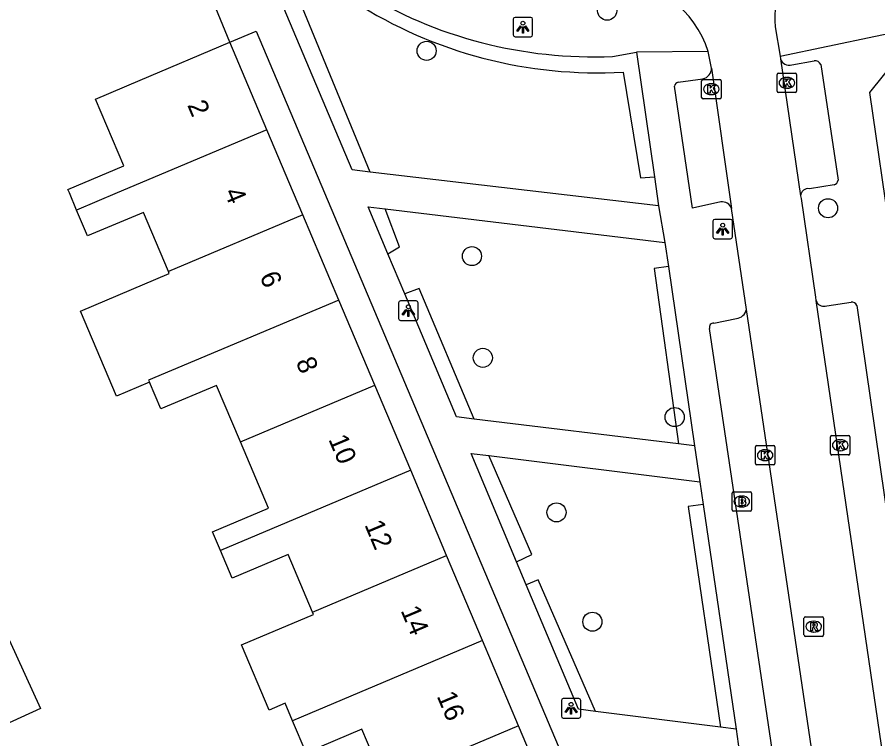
# Model space of a CAD drawing. Extents: x 162172 to 163187, y 382874 to 383684.
# Drawn here: x 162745.12 to 162789.24, y 383222 to 383259.01 of the extents above; entities that cross this region are included whole.
import ezdxf

# ---------------------------------------------------------------- set-up
doc = ezdxf.new("R2010")
doc.units = 0
for name, color, linetype in [('IMGEO_Boom', 7, 'Continuous'), ('IMGEO_Brandkraan', 7, 'Continuous'), ('IMGEO_Haag', 7, 'Continuous'), ('IMGEO_Kolk', 7, 'Continuous'), ('IMGEO_Lichtpunt', 7, 'Continuous'), ('IMGEO_Pand', 7, 'Continuous'), ('IMGEO_Pand_nummerreeks', 7, 'Continuous'), ('IMGEO_Rijbaan_lokaal_open', 7, 'Continuous'), ('IMGEO_Rioolput', 7, 'Continuous'), ('IMGEO_Voetpad_open', 7, 'Continuous')]:
    doc.layers.add(name, color=color, linetype=linetype)

msp = doc.modelspace()

# ---------------------------------------------------------------- linework, layer by layer
at = {"layer": 'IMGEO_Boom'}
for centre in [(162775.367, 383259.341), (162766.112, 383257.287), (162786.691, 383249.213), (162768.437, 383246.757), (162768.995, 383241.541), (162778.829, 383238.501), (162772.772, 383233.614), (162774.61, 383228.007)]:
    msp.add_circle(centre, 0.489, dxfattribs=at)
at = {"layer": 'IMGEO_Brandkraan'}
for p, q in [((162781.77, 383233.746), (162781.77, 383234.598)), ((162781.845, 383234.672), (162782.697, 383234.672)), ((162782.258, 383234.452), (162782.283, 383234.452)), ((162782.771, 383234.598), (162782.771, 383233.746)), ((162782.697, 383233.672), (162781.845, 383233.672)), ((162782.281, 383233.892), (162782.256, 383233.892))]:
    msp.add_line(p, q, dxfattribs=at)
for points in [[(162781.77, 383233.746), (162781.77, 383234.598)], [(162781.845, 383234.672), (162782.697, 383234.672)], [(162782.771, 383234.598), (162782.771, 383233.746)], [(162782.118, 383234.372), (162782.118, 383233.972), (162782.331, 383233.972)], [(162782.349, 383234.372), (162782.118, 383234.372)], [(162782.297, 383234.291), (162782.243, 383234.291), (162782.243, 383234.215)], [(162782.243, 383234.215), (162782.296, 383234.215)], [(162782.305, 383234.139), (162782.243, 383234.139), (162782.243, 383234.058)], [(162782.243, 383234.058), (162782.305, 383234.058)], [(162782.697, 383233.672), (162781.845, 383233.672)]]:
    msp.add_lwpolyline(points, dxfattribs=at)
for centre, radius, start, end in [((162781.847, 383234.596), 0.0765, 91.552, 178.448), ((162781.847, 383234.596), 0.0765, 91.552, 178.448), ((162782.695, 383234.596), 0.0765, 1.552, 88.448), ((162782.695, 383234.596), 0.0765, 1.552, 88.448), ((162782.298, 383234.253), 0.0379, 267.8285, 90.9355), ((162782.306, 383234.098), 0.0404, 269.8759, 90.5077), ((162782.337, 383234.223), 0.251, 268.6676, 293.5347), ((162782.353, 383234.227), 0.145, 59.4692, 91.5367), ((162782.378, 383234.274), 0.0922, 285.5137, 58.1501), ((162782.383, 383234.082), 0.105, 301.3115, 78.989), ((162781.847, 383233.748), 0.0765, 181.552, 268.448), ((162781.847, 383233.748), 0.0765, 181.552, 268.448), ((162782.695, 383233.748), 0.0765, 271.552, 358.448), ((162782.695, 383233.748), 0.0765, 271.552, 358.448)]:
    msp.add_arc(centre, radius, start, end, dxfattribs=at)
for centre, major_axis, ratio, start_param, end_param in [((162782.257, 383234.172), (-0.387, 0.002), 0.722429, 4.712389, 7.853982), ((162782.282, 383234.172), (-0.39, 0.002), 0.717154, 1.570796, 4.712389)]:
    msp.add_ellipse(centre, major_axis=major_axis, ratio=ratio, start_param=start_param, end_param=end_param, dxfattribs=at)
at = {"layer": 'IMGEO_Haag'}
for points in [[(162763.217, 383251.068), (162759.506, 383260.09), (162760.869, 383261.604)], [(162776.18, 383256.197), (162777.082, 383250.77), (162777.789, 383250.819)], [(162764.126, 383246.877), (162764.728, 383247.234), (162763.981, 383249.177)], [(162778.511, 383246.225), (162777.772, 383246.13), (162779.025, 383237.133)], [(162768.556, 383238.403), (162765.727, 383245.101), (162764.994, 383244.816)], [(162770.724, 383231.084), (162771.502, 383231.448), (162769.295, 383236.525)], [(162780.295, 383234.023), (162779.518, 383233.923), (162781.183, 383222.6)], [(162774.776, 383223.407), (162771.823, 383230.155), (162771.221, 383229.897)]]:
    msp.add_lwpolyline(points, dxfattribs=at)
msp.add_arc((162774.845, 383279.215), 23.057, 237.321, 273.3192, dxfattribs=at)
at = {"layer": 'IMGEO_Kolk'}
for p, q in [((162784.081, 383255.217), (162784.081, 383256.069)), ((162784.156, 383256.143), (162785.008, 383256.143)), ((162785.082, 383256.069), (162785.082, 383255.217)), ((162780.209, 383254.892), (162780.209, 383255.744)), ((162780.284, 383255.818), (162781.136, 383255.818)), ((162780.697, 383255.598), (162780.722, 383255.598)), ((162781.21, 383255.744), (162781.21, 383254.892)), ((162784.569, 383255.923), (162784.594, 383255.923)), ((162784.592, 383255.363), (162784.567, 383255.363)), ((162781.136, 383254.818), (162780.284, 383254.818)), ((162780.72, 383255.038), (162780.695, 383255.038)), ((162785.008, 383255.143), (162784.156, 383255.143)), ((162786.89, 383237.558), (162787.742, 383237.558)), ((162786.815, 383236.632), (162786.815, 383237.484)), ((162787.303, 383237.338), (162787.328, 383237.338)), ((162787.816, 383237.484), (162787.816, 383236.632)), ((162782.967, 383236.121), (162782.967, 383236.973)), ((162783.042, 383237.047), (162783.894, 383237.047)), ((162783.455, 383236.827), (162783.48, 383236.827)), ((162783.968, 383236.973), (162783.968, 383236.121)), ((162787.326, 383236.778), (162787.301, 383236.778)), ((162783.478, 383236.267), (162783.453, 383236.267)), ((162787.742, 383236.558), (162786.89, 383236.558)), ((162783.894, 383236.047), (162783.042, 383236.047))]:
    msp.add_line(p, q, dxfattribs=at)
for points in [[(162784.081, 383255.217), (162784.081, 383256.069)], [(162784.156, 383256.143), (162785.008, 383256.143)], [(162785.082, 383256.069), (162785.082, 383255.217)], [(162780.209, 383254.892), (162780.209, 383255.744)], [(162780.284, 383255.818), (162781.136, 383255.818)], [(162781.21, 383255.744), (162781.21, 383254.892)], [(162784.402, 383255.843), (162784.525, 383255.843), (162784.525, 383255.692), (162784.655, 383255.843), (162784.819, 383255.843), (162784.673, 383255.692), (162784.826, 383255.443), (162784.674, 383255.443), (162784.589, 383255.607), (162784.525, 383255.54), (162784.525, 383255.443), (162784.402, 383255.443), (162784.402, 383255.843)], [(162780.53, 383255.518), (162780.653, 383255.518), (162780.653, 383255.367), (162780.783, 383255.518), (162780.947, 383255.518), (162780.801, 383255.367), (162780.954, 383255.118), (162780.802, 383255.118), (162780.717, 383255.282), (162780.653, 383255.215), (162780.653, 383255.118), (162780.53, 383255.118), (162780.53, 383255.518)], [(162781.136, 383254.818), (162780.284, 383254.818)], [(162785.008, 383255.143), (162784.156, 383255.143)], [(162786.89, 383237.558), (162787.742, 383237.558)], [(162786.815, 383236.632), (162786.815, 383237.484)], [(162787.136, 383237.258), (162787.259, 383237.258), (162787.259, 383237.107), (162787.389, 383237.258), (162787.553, 383237.258), (162787.407, 383237.107), (162787.56, 383236.858), (162787.408, 383236.858), (162787.323, 383237.022), (162787.259, 383236.955), (162787.259, 383236.858), (162787.136, 383236.858), (162787.136, 383237.258)], [(162787.816, 383237.484), (162787.816, 383236.632)], [(162782.967, 383236.121), (162782.967, 383236.973)], [(162783.042, 383237.047), (162783.894, 383237.047)], [(162783.288, 383236.747), (162783.411, 383236.747), (162783.411, 383236.596), (162783.541, 383236.747), (162783.705, 383236.747), (162783.559, 383236.596), (162783.712, 383236.347), (162783.56, 383236.347), (162783.475, 383236.511), (162783.411, 383236.444), (162783.411, 383236.347), (162783.288, 383236.347), (162783.288, 383236.747)], [(162783.968, 383236.973), (162783.968, 383236.121)], [(162787.742, 383236.558), (162786.89, 383236.558)], [(162783.894, 383236.047), (162783.042, 383236.047)]]:
    msp.add_lwpolyline(points, dxfattribs=at)
for centre, start, end in [((162784.158, 383256.067), 91.552, 178.448), ((162784.158, 383256.067), 91.552, 178.448), ((162785.006, 383256.067), 1.552, 88.448), ((162785.006, 383256.067), 1.552, 88.448), ((162780.286, 383255.742), 91.552, 178.448), ((162780.286, 383255.742), 91.552, 178.448), ((162781.134, 383255.742), 1.552, 88.448), ((162781.134, 383255.742), 1.552, 88.448), ((162784.158, 383255.219), 181.552, 268.448), ((162784.158, 383255.219), 181.552, 268.448), ((162785.006, 383255.219), 271.552, 358.448), ((162785.006, 383255.219), 271.552, 358.448), ((162780.286, 383254.894), 181.552, 268.448), ((162780.286, 383254.894), 181.552, 268.448), ((162781.134, 383254.894), 271.552, 358.448), ((162781.134, 383254.894), 271.552, 358.448), ((162786.892, 383237.482), 91.552, 178.448), ((162786.892, 383237.482), 91.552, 178.448), ((162787.74, 383237.482), 1.552, 88.448), ((162787.74, 383237.482), 1.552, 88.448), ((162783.044, 383236.971), 91.552, 178.448), ((162783.044, 383236.971), 91.552, 178.448), ((162783.892, 383236.971), 1.552, 88.448), ((162783.892, 383236.971), 1.552, 88.448), ((162786.892, 383236.634), 181.552, 268.448), ((162786.892, 383236.634), 181.552, 268.448), ((162787.74, 383236.634), 271.552, 358.448), ((162787.74, 383236.634), 271.552, 358.448), ((162783.044, 383236.123), 181.552, 268.448), ((162783.044, 383236.123), 181.552, 268.448), ((162783.892, 383236.123), 271.552, 358.448), ((162783.892, 383236.123), 271.552, 358.448)]:
    msp.add_arc(centre, 0.0765, start, end, dxfattribs=at)
for centre, major_axis, ratio, start_param, end_param in [((162780.696, 383255.318), (-0.387, 0.002), 0.722429, 4.712389, 7.853982), ((162780.721, 383255.318), (-0.39, 0.002), 0.717154, 1.570796, 4.712389), ((162784.568, 383255.643), (-0.387, 0.002), 0.722429, 4.712389, 7.853982), ((162784.593, 383255.643), (-0.39, 0.002), 0.717154, 1.570796, 4.712389), ((162787.302, 383237.058), (-0.387, 0.002), 0.722429, 4.712389, 7.853982), ((162787.327, 383237.058), (-0.39, 0.002), 0.717154, 1.570796, 4.712389), ((162783.454, 383236.547), (-0.387, 0.002), 0.722429, 4.712389, 7.853982), ((162783.479, 383236.547), (-0.39, 0.002), 0.717154, 1.570796, 4.712389)]:
    msp.add_ellipse(centre, major_axis=major_axis, ratio=ratio, start_param=start_param, end_param=end_param, dxfattribs=at)
at = {"layer": 'IMGEO_Lichtpunt'}
for p, q in [((162770.549, 383258.905), (162770.549, 383258.098)), ((162770.549, 383258.905), (162770.549, 383258.098)), ((162771.451, 383259), (162770.643, 383259)), ((162771.451, 383259), (162770.643, 383259)), ((162771.545, 383258.098), (162771.545, 383258.905)), ((162771.545, 383258.098), (162771.545, 383258.905)), ((162770.643, 383258.004), (162771.451, 383258.004)), ((162770.643, 383258.004), (162771.451, 383258.004)), ((162780.793, 383248.546), (162780.793, 383247.739)), ((162780.793, 383248.546), (162780.793, 383247.739)), ((162781.695, 383248.641), (162780.887, 383248.641)), ((162781.695, 383248.641), (162780.887, 383248.641)), ((162781.789, 383247.739), (162781.789, 383248.546)), ((162781.789, 383247.739), (162781.789, 383248.546)), ((162780.887, 383247.645), (162781.695, 383247.645)), ((162780.887, 383247.645), (162781.695, 383247.645)), ((162764.677, 383244.363), (162764.677, 383243.556)), ((162764.677, 383244.363), (162764.677, 383243.556)), ((162765.579, 383244.458), (162764.771, 383244.458)), ((162765.579, 383244.458), (162764.771, 383244.458)), ((162765.673, 383243.556), (162765.673, 383244.363)), ((162765.673, 383243.556), (162765.673, 383244.363)), ((162764.771, 383243.462), (162765.579, 383243.462)), ((162764.771, 383243.462), (162765.579, 383243.462)), ((162773.02, 383223.97), (162773.02, 383223.163)), ((162773.02, 383223.97), (162773.02, 383223.163)), ((162773.922, 383224.065), (162773.114, 383224.065)), ((162773.922, 383224.065), (162773.114, 383224.065)), ((162774.016, 383223.163), (162774.016, 383223.97)), ((162774.016, 383223.163), (162774.016, 383223.97)), ((162773.114, 383223.069), (162773.922, 383223.069)), ((162773.114, 383223.069), (162773.922, 383223.069))]:
    msp.add_line(p, q, dxfattribs=at)
for points in [[(162770.923, 383258.569), (162770.962, 383258.541), (162770.774, 383258.279), (162770.736, 383258.306), (162770.923, 383258.569)], [(162771.025, 383258.521), (162771.072, 383258.521), (162771.072, 383258.199), (162771.025, 383258.199), (162771.025, 383258.521)], [(162771.135, 383258.541), (162771.173, 383258.568), (162771.36, 383258.306), (162771.321, 383258.278), (162771.135, 383258.541)], [(162781.167, 383248.21), (162781.206, 383248.182), (162781.018, 383247.92), (162780.98, 383247.947), (162781.167, 383248.21)], [(162781.269, 383248.162), (162781.316, 383248.162), (162781.316, 383247.84), (162781.269, 383247.84), (162781.269, 383248.162)], [(162781.379, 383248.182), (162781.417, 383248.209), (162781.604, 383247.947), (162781.565, 383247.919), (162781.379, 383248.182)], [(162765.051, 383244.027), (162765.09, 383243.999), (162764.902, 383243.737), (162764.864, 383243.764), (162765.051, 383244.027)], [(162765.153, 383243.979), (162765.2, 383243.979), (162765.2, 383243.657), (162765.153, 383243.657), (162765.153, 383243.979)], [(162765.263, 383243.999), (162765.301, 383244.026), (162765.488, 383243.764), (162765.449, 383243.736), (162765.263, 383243.999)], [(162773.394, 383223.634), (162773.433, 383223.606), (162773.245, 383223.344), (162773.207, 383223.371), (162773.394, 383223.634)], [(162773.496, 383223.586), (162773.543, 383223.586), (162773.543, 383223.264), (162773.496, 383223.264), (162773.496, 383223.586)], [(162773.606, 383223.606), (162773.644, 383223.633), (162773.831, 383223.371), (162773.792, 383223.343), (162773.606, 383223.606)]]:
    msp.add_lwpolyline(points, dxfattribs=at)
for centre in [(162771.048, 383258.703), (162781.292, 383248.344), (162765.176, 383244.161), (162773.519, 383223.768)]:
    msp.add_circle(centre, 0.0994, dxfattribs=at)
for centre, start, end in [((162770.643, 383258.905), 90, 180), ((162770.643, 383258.905), 90, 180), ((162771.451, 383258.905), 0, 90), ((162771.451, 383258.905), 0, 90), ((162770.643, 383258.098), 180, 270), ((162770.643, 383258.098), 180, 270), ((162771.451, 383258.098), 270, 0), ((162771.451, 383258.098), 270, 360), ((162780.887, 383248.546), 90, 180), ((162780.887, 383248.546), 90, 180), ((162781.695, 383248.546), 0, 90), ((162781.695, 383248.546), 0, 90), ((162780.887, 383247.739), 180, 270), ((162780.887, 383247.739), 180, 270), ((162781.695, 383247.739), 270, 0), ((162781.695, 383247.739), 270, 360), ((162764.771, 383244.363), 90, 180), ((162764.771, 383244.363), 90, 180), ((162765.579, 383244.363), 0, 90), ((162765.579, 383244.363), 0, 90), ((162764.771, 383243.556), 180, 270), ((162764.771, 383243.556), 180, 270), ((162765.579, 383243.556), 270, 0), ((162765.579, 383243.556), 270, 360), ((162773.114, 383223.97), 90, 180), ((162773.114, 383223.97), 90, 180), ((162773.922, 383223.97), 0, 90), ((162773.922, 383223.97), 0, 90), ((162773.114, 383223.163), 180, 270), ((162773.114, 383223.163), 180, 270), ((162773.922, 383223.163), 270, 0), ((162773.922, 383223.163), 270, 360)]:
    msp.add_arc(centre, 0.0946, start, end, dxfattribs=at)
at = {"layer": 'IMGEO_Pand'}
for points in [[(162748.166, 383249.121), (162747.794, 383250), (162747.721, 383250.174), (162750.581, 383251.382), (162749.134, 383254.803), (162751.426, 383255.781), (162756.031, 383257.726)], [(162757.924, 383253.24), (162756.031, 383257.726)], [(162757.924, 383253.24), (162750.248, 383250), (162748.166, 383249.121)], [(162759.767, 383248.873), (162759.291, 383250), (162757.924, 383253.24)], [(162752.872, 383245.962), (162751.589, 383248.998), (162748.729, 383247.79), (162748.166, 383249.121)], [(162759.767, 383248.873), (162752.872, 383245.962)], [(162761.609, 383244.506), (162759.767, 383248.873)], [(162751.898, 383240.292), (162750.215, 383239.58), (162748.372, 383243.936), (162752.916, 383245.858), (162752.872, 383245.962)], [(162761.609, 383244.506), (162751.857, 383240.39), (162751.898, 383240.292)], [(162763.452, 383240.138), (162761.609, 383244.506)], [(162756.564, 383237.231), (162755.34, 383240.126), (162752.48, 383238.917), (162751.898, 383240.292)], [(162756.564, 383237.231), (162763.452, 383240.138)], [(162765.295, 383235.772), (162763.452, 383240.138)], [(162755.55, 383231.659), (162755.142, 383232.623), (162758.002, 383233.831), (162756.564, 383237.231)], [(162765.295, 383235.772), (162755.55, 383231.659)], [(162767.137, 383231.405), (162765.295, 383235.772)], [(162760.256, 383228.5), (162759.01, 383231.447), (162756.15, 383230.239), (162755.55, 383231.659)], [(162760.256, 383228.5), (162767.137, 383231.405)], [(162768.98, 383227.038), (162767.137, 383231.405)], [(162759.237, 383222.925), (162758.857, 383223.823), (162758.042, 383223.479), (162756.624, 383226.83), (162760.305, 383228.385), (162760.256, 383228.5)], [(162744.712, 383227.084), (162746.313, 383223.562), (162743.868, 383222.451)], [(162768.98, 383227.038), (162759.237, 383222.925)], [(162770.823, 383222.671), (162768.98, 383227.038)], [(162763.948, 383219.768), (162762.796, 383222.492), (162759.932, 383221.282), (162759.237, 383222.925)], [(162770.823, 383222.671), (162763.948, 383219.768)], [(162772.666, 383218.303), (162770.823, 383222.671)]]:
    msp.add_lwpolyline(points, dxfattribs=at)
at = {"layer": 'IMGEO_Rijbaan_lokaal_open'}
for points in [[(162783.988, 383258.519), (162784.237, 383257.006)], [(162780.72, 383256.395), (162780.54, 383257.245)], [(162784.237, 383257.006), (162784.257, 383256.869)], [(162784.257, 383256.869), (162785.285, 383249.85)], [(162780.72, 383256.395), (162781.746, 383249.202)], [(162785.285, 383249.85), (162785.306, 383249.706), (162786.043, 383244.65), (162786.068, 383244.482)], [(162782.511, 383244.018), (162781.746, 383249.202)], [(162786.068, 383244.482), (162789.498, 383221.074)], [(162785.652, 383211.864), (162785.97, 383214.404), (162786.16, 383216.464), (162786.163, 383218.532), (162785.981, 383220.593), (162782.511, 383244.018)]]:
    msp.add_lwpolyline(points, dxfattribs=at)
for centre, radius, start, end in [((162787.075, 383258.973), 3.12, 102.2341, 188.3569), ((162775.708, 383255.805), 5.042, 16.5909, 90.8812)]:
    msp.add_arc(centre, radius, start, end, dxfattribs=at)
at = {"layer": 'IMGEO_Rioolput'}
for p, q in [((162785.534, 383228.256), (162786.386, 383228.256)), ((162785.459, 383227.33), (162785.459, 383228.182)), ((162785.947, 383228.036), (162785.972, 383228.036)), ((162786.46, 383228.182), (162786.46, 383227.33)), ((162785.97, 383227.476), (162785.945, 383227.476)), ((162786.386, 383227.256), (162785.534, 383227.256))]:
    msp.add_line(p, q, dxfattribs=at)
for points in [[(162785.534, 383228.256), (162786.386, 383228.256)], [(162785.459, 383227.33), (162785.459, 383228.182)], [(162786.048, 383227.954), (162785.796, 383227.956), (162785.796, 383227.556)], [(162785.974, 383227.875), (162785.92, 383227.875), (162785.92, 383227.794)], [(162786.46, 383228.182), (162786.46, 383227.33)], [(162785.796, 383227.556), (162785.92, 383227.556), (162785.92, 383227.718), (162785.931, 383227.718)], [(162785.92, 383227.794), (162785.972, 383227.794)], [(162785.978, 383227.689), (162786.049, 383227.556), (162786.189, 383227.556), (162786.124, 383227.682)], [(162786.386, 383227.256), (162785.534, 383227.256)]]:
    msp.add_lwpolyline(points, dxfattribs=at)
for centre, radius, start, end in [((162785.536, 383228.18), 0.0765, 91.552, 178.448), ((162785.536, 383228.18), 0.0765, 91.552, 178.448), ((162786.384, 383228.18), 0.0765, 1.552, 88.448), ((162786.384, 383228.18), 0.0765, 1.552, 88.448), ((162785.98, 383227.779), 0.0964, 77.0061, 93.1865), ((162785.994, 383227.836), 0.0378, 276.6634, 79.6772), ((162786.047, 383227.844), 0.109, 350.3612, 89.416), ((162786.045, 383227.844), 0.112, 277.5842, 350.9817), ((162785.93, 383227.665), 0.0533, 26.0293, 88.6989), ((162785.956, 383227.983), 0.19, 274.7715, 282.9687), ((162786.029, 383227.629), 0.108, 29.5134, 73.7905), ((162785.536, 383227.332), 0.0765, 181.552, 268.448), ((162785.536, 383227.332), 0.0765, 181.552, 268.448), ((162786.384, 383227.332), 0.0765, 271.552, 358.448), ((162786.384, 383227.332), 0.0765, 271.552, 358.448)]:
    msp.add_arc(centre, radius, start, end, dxfattribs=at)
for centre, major_axis, ratio, start_param, end_param in [((162785.946, 383227.756), (-0.387, 0.002), 0.722429, 4.712389, 7.853982), ((162785.971, 383227.756), (-0.39, 0.002), 0.717154, 1.570796, 4.712389)]:
    msp.add_ellipse(centre, major_axis=major_axis, ratio=ratio, start_param=start_param, end_param=end_param, dxfattribs=at)
at = {"layer": 'IMGEO_Voetpad_open'}
for points in [[(162763.217, 383251.068), (162762.291, 383251.176), (162758.434, 383260.348), (162760.352, 383262.006)], [(162756.031, 383257.726), (162754.819, 383260.648)], [(162756.031, 383257.726), (162757.374, 383258.3), (162760.88, 383250), (162775.931, 383214.365), (162774.558, 383213.819)], [(162784.237, 383257.006), (162791.577, 383258.544)], [(162791.058, 383239.835), (162788.83, 383255.15), (162791.577, 383258.544)], [(162775.633, 383256.999), (162776.875, 383257.212)], [(162780.54, 383257.245), (162776.875, 383257.212)], [(162776.875, 383257.212), (162777.789, 383250.819)], [(162784.831, 383256.563), (162785.979, 383256.772)], [(162786.318, 383256.577), (162787.204, 383250.653)], [(162779.006, 383255.671), (162780.275, 383255.856)], [(162781.193, 383249.536), (162779.748, 383249.218), (162778.818, 383255.477)], [(162778, 383249.343), (162763.217, 383251.068)], [(162777.789, 383250.819), (162778, 383249.343)], [(162787.005, 383250.416), (162785.736, 383250.216)], [(162764.126, 383246.877), (162763.113, 383249.281), (162763.981, 383249.177)], [(162763.981, 383249.177), (162778.331, 383247.459)], [(162778, 383249.343), (162778.331, 383247.459)], [(162778.331, 383247.459), (162778.511, 383246.225)], [(162764.994, 383244.816), (162764.126, 383246.877)], [(162778.511, 383246.225), (162779.854, 383237.032)], [(162768.556, 383238.403), (162767.649, 383238.513), (162764.994, 383244.816)], [(162786.068, 383244.482), (162786.109, 383244.395)], [(162786.622, 383244.208), (162787.873, 383244.396)], [(162788.168, 383244.227), (162791.474, 383221.369)], [(162780.844, 383243.323), (162781.998, 383243.552)], [(162780.29, 383185.456), (162780.624, 383187.419), (162784.036, 383215.116), (162784.186, 383216.843), (162784.176, 383218.577), (162784.004, 383220.303), (162780.623, 383243.044)], [(162779.025, 383237.133), (162768.556, 383238.403)], [(162779.854, 383237.032), (162779.025, 383237.133)], [(162770.724, 383231.084), (162768.399, 383236.636), (162769.295, 383236.525)], [(162779.854, 383237.032), (162780.126, 383235.179)], [(162769.295, 383236.525), (162780.126, 383235.179)], [(162780.126, 383235.179), (162780.295, 383234.023)], [(162780.295, 383234.023), (162781.978, 383222.5)], [(162771.221, 383229.897), (162770.724, 383231.084)], [(162774.776, 383223.407), (162773.892, 383223.518), (162771.221, 383229.897)], [(162781.183, 383222.6), (162774.776, 383223.407)], [(162781.978, 383222.5), (162781.183, 383222.6)], [(162781.978, 383222.5), (162782.232, 383220.621)]]:
    msp.add_lwpolyline(points, dxfattribs=at)
for centre, radius, start, end in [((162774.664, 383279.865), 22.886, 238.4807, 272.4277), ((162784.695, 383257), 0.457, 196.5965, 287.2792), ((162786.019, 383256.449), 0.325, 23.1096, 97.0736), ((162780.166, 383256.399), 0.554, 281.3108, 359.6029), ((162779.054, 383255.436), 0.239, 101.5673, 170.2324), ((162786.93, 383250.681), 0.275, 285.8059, 354.1563), ((162785.672, 383249.835), 0.387, 80.4093, 177.7114), ((162781.264, 383249.029), 0.512, 19.7866, 97.9512), ((162786.484, 383244.628), 0.442, 211.8012, 288.1429), ((162787.915, 383244.128), 0.271, 21.369, 99.0158), ((162781.913, 383244.161), 0.615, 277.9373, 346.5656), ((162780.818, 383243.116), 0.208, 82.8541, 200.3794)]:
    msp.add_arc(centre, radius, start, end, dxfattribs=at)

# ---------------------------------------------------------------- texts
at = {"layer": 'IMGEO_Pand_nummerreeks'}
for s, rotation, p in [('2', 292.8778, (162753.827, 383254.51)), ('4', 292.8811, (162755.716, 383250.035)), ('6', 292.878, (162757.534, 383245.729)), ('8', 292.878, (162759.388, 383241.334)), ('10', 292.8778, (162761.062, 383237.367)), ('12', 292.878, (162762.911, 383232.982)), ('14', 292.8778, (162764.766, 383228.588)), ('16', 292.8778, (162766.618, 383224.197))]:
    msp.add_text(s, height=1, rotation=rotation, dxfattribs=at).set_placement(p)

doc.saveas('drawing.dxf')
